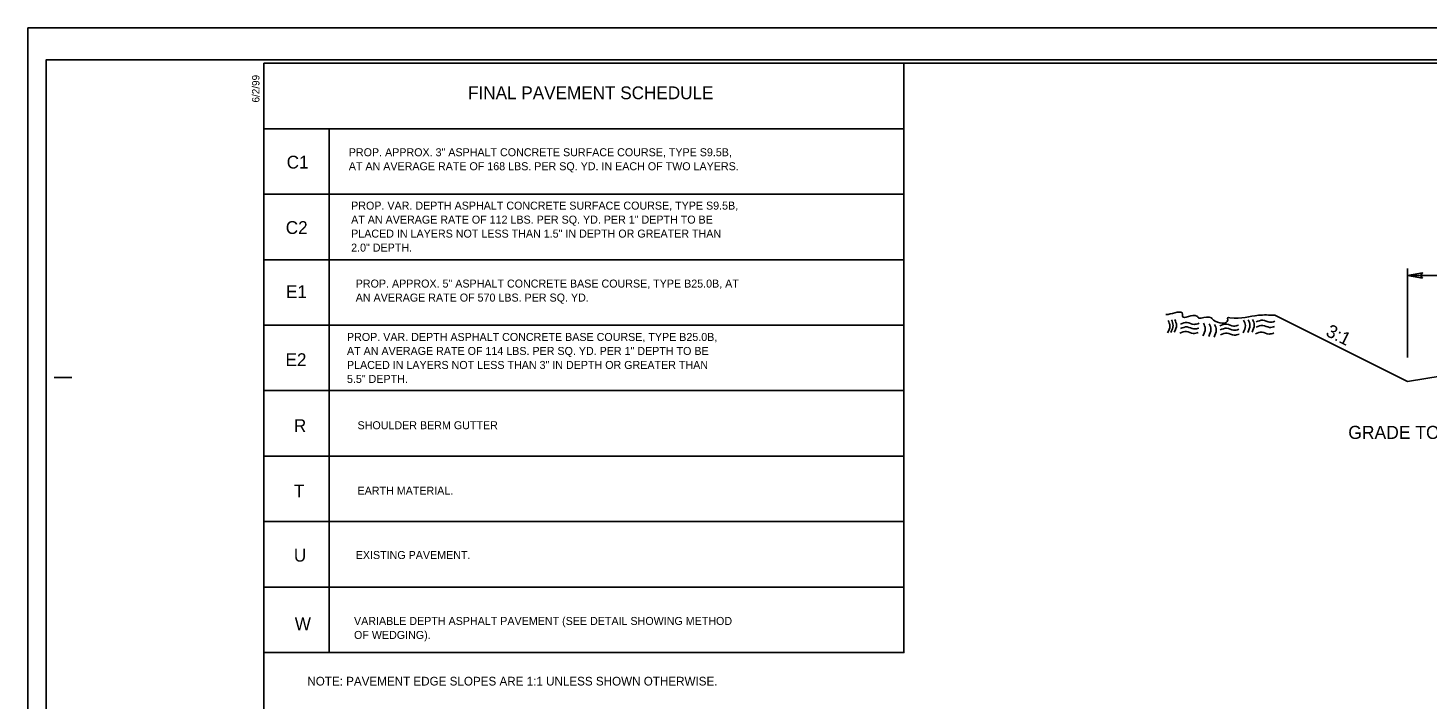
# Model space of a CAD drawing. Extents: x 1734085 to 1734267, y 541107 to 541226.
# Drawn here: x 1734084.6 to 1734191.6, y 541174.6 to 541225.9 of the extents above; entities that cross this region are included whole.
import ezdxf

# ---------------------------------------------------------------- set-up
doc = ezdxf.new("R2010")
doc.units = 0
for name, color, linetype in [('Old_Level_2', 7, 'Continuous'), ('Prop Dimension', 7, 'Continuous'), ('Prop Pavement Schedule Description CELL', 7, 'Continuous'), ('Prop Terminator CELL', 7, 'Continuous'), ('Sheet Cutting Line CELL', 7, 'Continuous'), ('Sheet Plot Border Inside CELL', 7, 'Continuous'), ('Sheet Plot Border Outside CELL', 7, 'Continuous'), ('Sheet Typical CELL', 7, 'Continuous'), ('Typical Slope Point Local CELL', 7, 'Continuous'), ('Typical Text General CELL', 7, 'Continuous')]:
    doc.layers.add(name, color=color, linetype=linetype)

msp = doc.modelspace()

# ---------------------------------------------------------------- linework, layer by layer
at = {"layer": 'Old_Level_2'}
for points in [[(1734171.64, 541203.96), (1734171.82, 541203.98), (1734172.92, 541204), (1734172.92, 541203.84), (1734174.02, 541203.85), (1734174.18, 541203.7), (1734174.33, 541203.7), (1734175.12, 541203.71), (1734175.28, 541203.55), (1734176.37, 541203.57), (1734176.37, 541203.72), (1734176.53, 541203.73), (1734178.72, 541203.91), (1734179.97, 541203.92)], [(1734171.82, 541203.52), (1734171.95, 541203.1), (1734171.78, 541202.56)], [(1734172.07, 541203.56), (1734172.19, 541203.14), (1734172.02, 541202.6)], [(1734172.33, 541203.58), (1734172.46, 541203.16), (1734172.29, 541202.62)], [(1734172.75, 541202.89), (1734173.26, 541203.02), (1734173.78, 541202.87), (1734174.17, 541202.94)], [(1734172.76, 541203.24), (1734173.27, 541203.37), (1734173.8, 541203.22), (1734174.18, 541203.3)], [(1734174.53, 541203.31), (1734174.65, 541202.89), (1734174.48, 541202.34)], [(1734174.96, 541203.26), (1734175.09, 541202.84), (1734174.92, 541202.3)], [(1734175.37, 541203.21), (1734175.5, 541202.79), (1734175.33, 541202.25)], [(1734175.78, 541203.1), (1734176.29, 541203.23), (1734176.82, 541203.08), (1734177.2, 541203.16)], [(1734177.59, 541203.54), (1734177.72, 541203.12), (1734177.55, 541202.57)], [(1734177.94, 541203.56), (1734178.07, 541203.14), (1734177.9, 541202.59)], [(1734178.28, 541203.6), (1734178.4, 541203.18), (1734178.23, 541202.63)], [(1734178.54, 541203.01), (1734179.05, 541203.14), (1734179.57, 541202.99), (1734179.96, 541203.06)], [(1734178.55, 541203.4), (1734179.06, 541203.53), (1734179.59, 541203.38), (1734179.97, 541203.45)], [(1734172.7, 541202.54), (1734173.21, 541202.67), (1734173.74, 541202.52), (1734174.12, 541202.59)], [(1734175.79, 541202.79), (1734176.29, 541202.92), (1734176.82, 541202.77), (1734177.21, 541202.84)], [(1734175.83, 541202.42), (1734176.33, 541202.55), (1734176.86, 541202.4), (1734177.25, 541202.47)], [(1734178.49, 541202.5), (1734179, 541202.63), (1734179.53, 541202.48), (1734179.91, 541202.56)]]:
    msp.add_spline(points, degree=3, dxfattribs=at)
at = {"layer": 'Prop Dimension'}
for p, q in [((1734190.13, 541200.68), (1734190.13, 541207.48)), ((1734190.13, 541206.95), (1734198.13, 541206.95))]:
    msp.add_line(p, q, dxfattribs=at)
at = {"layer": 'Prop Pavement Schedule Description CELL'}
msp.add_line((1734102.68, 541178.13), (1734102.68, 541178.13), dxfattribs=at)
msp.add_lwpolyline([(1734102.68, 541223.18), (1734151.61, 541223.18), (1734151.61, 541218.17), (1734102.68, 541218.17)], close=True, dxfattribs=at)
for points in [[(1734107.68, 541213.17), (1734102.68, 541213.17), (1734102.68, 541218.17), (1734151.61, 541218.17), (1734151.61, 541213.17), (1734107.68, 541213.17), (1734107.68, 541218.17)], [(1734107.68, 541208.16), (1734102.68, 541208.16), (1734102.68, 541213.17), (1734151.61, 541213.17), (1734151.61, 541208.16), (1734107.68, 541208.16), (1734107.68, 541213.17)], [(1734107.68, 541203.16), (1734102.68, 541203.16), (1734102.68, 541208.16), (1734151.61, 541208.16), (1734151.61, 541203.16), (1734107.68, 541203.16), (1734107.68, 541208.16)], [(1734107.68, 541198.15), (1734102.68, 541198.15), (1734102.68, 541203.16), (1734151.61, 541203.16), (1734151.61, 541198.15), (1734107.68, 541198.15), (1734107.68, 541203.16)], [(1734107.68, 541193.15), (1734102.68, 541193.15), (1734102.68, 541198.15), (1734151.61, 541198.15), (1734151.61, 541193.15), (1734107.68, 541193.15), (1734107.68, 541198.15)], [(1734107.68, 541188.14), (1734102.68, 541188.14), (1734102.68, 541193.15), (1734151.61, 541193.15), (1734151.61, 541188.14), (1734107.68, 541188.14), (1734107.68, 541193.15)], [(1734107.68, 541183.14), (1734102.68, 541183.14), (1734102.68, 541188.14), (1734151.61, 541188.14), (1734151.61, 541183.14), (1734107.68, 541183.14), (1734107.68, 541188.14)], [(1734107.68, 541178.13), (1734102.68, 541178.13), (1734102.68, 541183.14), (1734151.61, 541183.14), (1734151.61, 541178.13), (1734107.68, 541178.13), (1734107.68, 541183.14)]]:
    msp.add_lwpolyline(points, dxfattribs=at)
at = {"layer": 'Prop Terminator CELL'}
msp.add_lwpolyline([(1734191.26, 541206.76), (1734190.13, 541206.95), (1734191.27, 541207.15), (1734191.12, 541206.95)], close=True, dxfattribs=at)
at = {"layer": 'Sheet Cutting Line CELL'}
for p, q in [((1734266.51, 541225.88), (1734084.64, 541225.88)), ((1734084.64, 541225.88), (1734084.64, 541107.08))]:
    msp.add_line(p, q, dxfattribs=at)
at = {"layer": 'Sheet Plot Border Inside CELL'}
msp.add_lwpolyline([(1734266.03, 541223.45), (1734086.04, 541223.45), (1734086.04, 541109.5), (1734266.03, 541109.5)], close=True, dxfattribs=at)
at = {"layer": 'Sheet Plot Border Outside CELL'}
msp.add_lwpolyline([(1734266.51, 541225.88), (1734084.64, 541225.88), (1734084.64, 541107.08), (1734266.51, 541107.08)], close=True, dxfattribs=at)
at = {"layer": 'Sheet Typical CELL'}
msp.add_line((1734086.64, 541199.15), (1734087.99, 541199.15), dxfattribs=at)
msp.add_lwpolyline([(1734264.68, 541223.18), (1734102.68, 541223.18), (1734102.68, 541109.78), (1734264.68, 541109.78)], close=True, dxfattribs=at)
at = {"layer": 'Typical Slope Point Local CELL'}
for p in [(1734179.97, 541203.92), (1734198.13, 541200.17)]:
    msp.add_line(p, (1734190.13, 541198.84), dxfattribs=at)

# ---------------------------------------------------------------- texts
at = {"layer": 'Prop Pavement Schedule Description CELL'}
for s, height, p in [('FINAL PAVEMENT SCHEDULE', 0.9787, (1734118.29, 541220.43)), ('C1', 0.979, (1734104.42, 541215.13)), ('PROP. APPROX. 3" ASPHALT CONCRETE SURFACE COURSE, TYPE S9.5B,', 0.6117, (1734109.17, 541216.07)), ('AT AN AVERAGE RATE OF 168 LBS. PER SQ. YD. IN EACH OF TWO LAYERS.', 0.6117, (1734109.17, 541215)), ('PROP. VAR. DEPTH ASPHALT CONCRETE SURFACE COURSE, TYPE S9.5B,', 0.6117, (1734109.35, 541211.99)), ('C2', 0.979, (1734104.35, 541210.13)), ('AT AN AVERAGE RATE OF 112 LBS. PER SQ. YD. PER 1" DEPTH TO BE', 0.6117, (1734109.35, 541210.92)), ('PLACED IN LAYERS NOT LESS THAN 1.5" IN DEPTH OR GREATER THAN', 0.6117, (1734109.35, 541209.85)), ('2.0" DEPTH.', 0.6117, (1734109.35, 541208.78)), ('PROP. APPROX. 5" ASPHALT CONCRETE BASE COURSE, TYPE B25.0B, AT', 0.6117, (1734109.7, 541206.03)), ('E1', 0.979, (1734104.37, 541205.23)), ('AN AVERAGE RATE OF 570 LBS. PER SQ. YD.', 0.6117, (1734109.7, 541204.96)), ('PROP. VAR. DEPTH ASPHALT CONCRETE BASE COURSE, TYPE B25.0B,', 0.6117, (1734109.03, 541201.95)), ('E2', 0.979, (1734104.33, 541200.03)), ('AT AN AVERAGE RATE OF 114 LBS. PER SQ. YD. PER 1" DEPTH TO BE', 0.6117, (1734109.03, 541200.88)), ('PLACED IN LAYERS NOT LESS THAN 3" IN DEPTH OR GREATER THAN', 0.6117, (1734109.03, 541199.81)), ('5.5" DEPTH.', 0.6117, (1734109.03, 541198.74)), ('R', 0.979, (1734104.97, 541194.99)), ('SHOULDER BERM GUTTER', 0.6117, (1734109.84, 541195.2)), ('T', 0.979, (1734104.98, 541189.99)), ('EARTH MATERIAL.', 0.6117, (1734109.84, 541190.2)), ('U', 0.979, (1734104.97, 541185.08)), ('EXISTING PAVEMENT.', 0.6117, (1734109.7, 541185.28)), ('W', 0.979, (1734105.04, 541179.84)), ('VARIABLE DEPTH ASPHALT PAVEMENT (SEE DETAIL SHOWING METHOD', 0.6117, (1734109.57, 541180.24)), ('OF WEDGING).', 0.6117, (1734109.57, 541179.17)), ('NOTE: PAVEMENT EDGE SLOPES ARE 1:1 UNLESS SHOWN OTHERWISE.', 0.6657, (1734106, 541175.61))]:
    msp.add_text(s, height=height, dxfattribs=at).set_placement(p)
at = {"layer": 'Sheet Typical CELL'}
msp.add_text('6/2/99', height=0.567, rotation=90, dxfattribs=at).set_placement((1734102.34, 541220.18))
at = {"layer": 'Typical Slope Point Local CELL'}
msp.add_text('3:1', height=1, rotation=333.435, dxfattribs=at).set_placement((1734183.8, 541202.38))
at = {"layer": 'Typical Text General CELL'}
msp.add_text('GRADE TO THIS LINE', height=1, dxfattribs=at).set_placement((1734185.59, 541194.46))

doc.saveas('drawing.dxf')
